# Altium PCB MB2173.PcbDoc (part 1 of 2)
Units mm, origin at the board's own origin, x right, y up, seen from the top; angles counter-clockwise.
Board outline 55.25 x 31 mm, 2 copper layers (Top Layer, Bottom Layer), stack 0.603 mm thick; 45 components, 48 nets, 188 pads, 868 vias.
Unrouted connection lines stored in the file: 99.
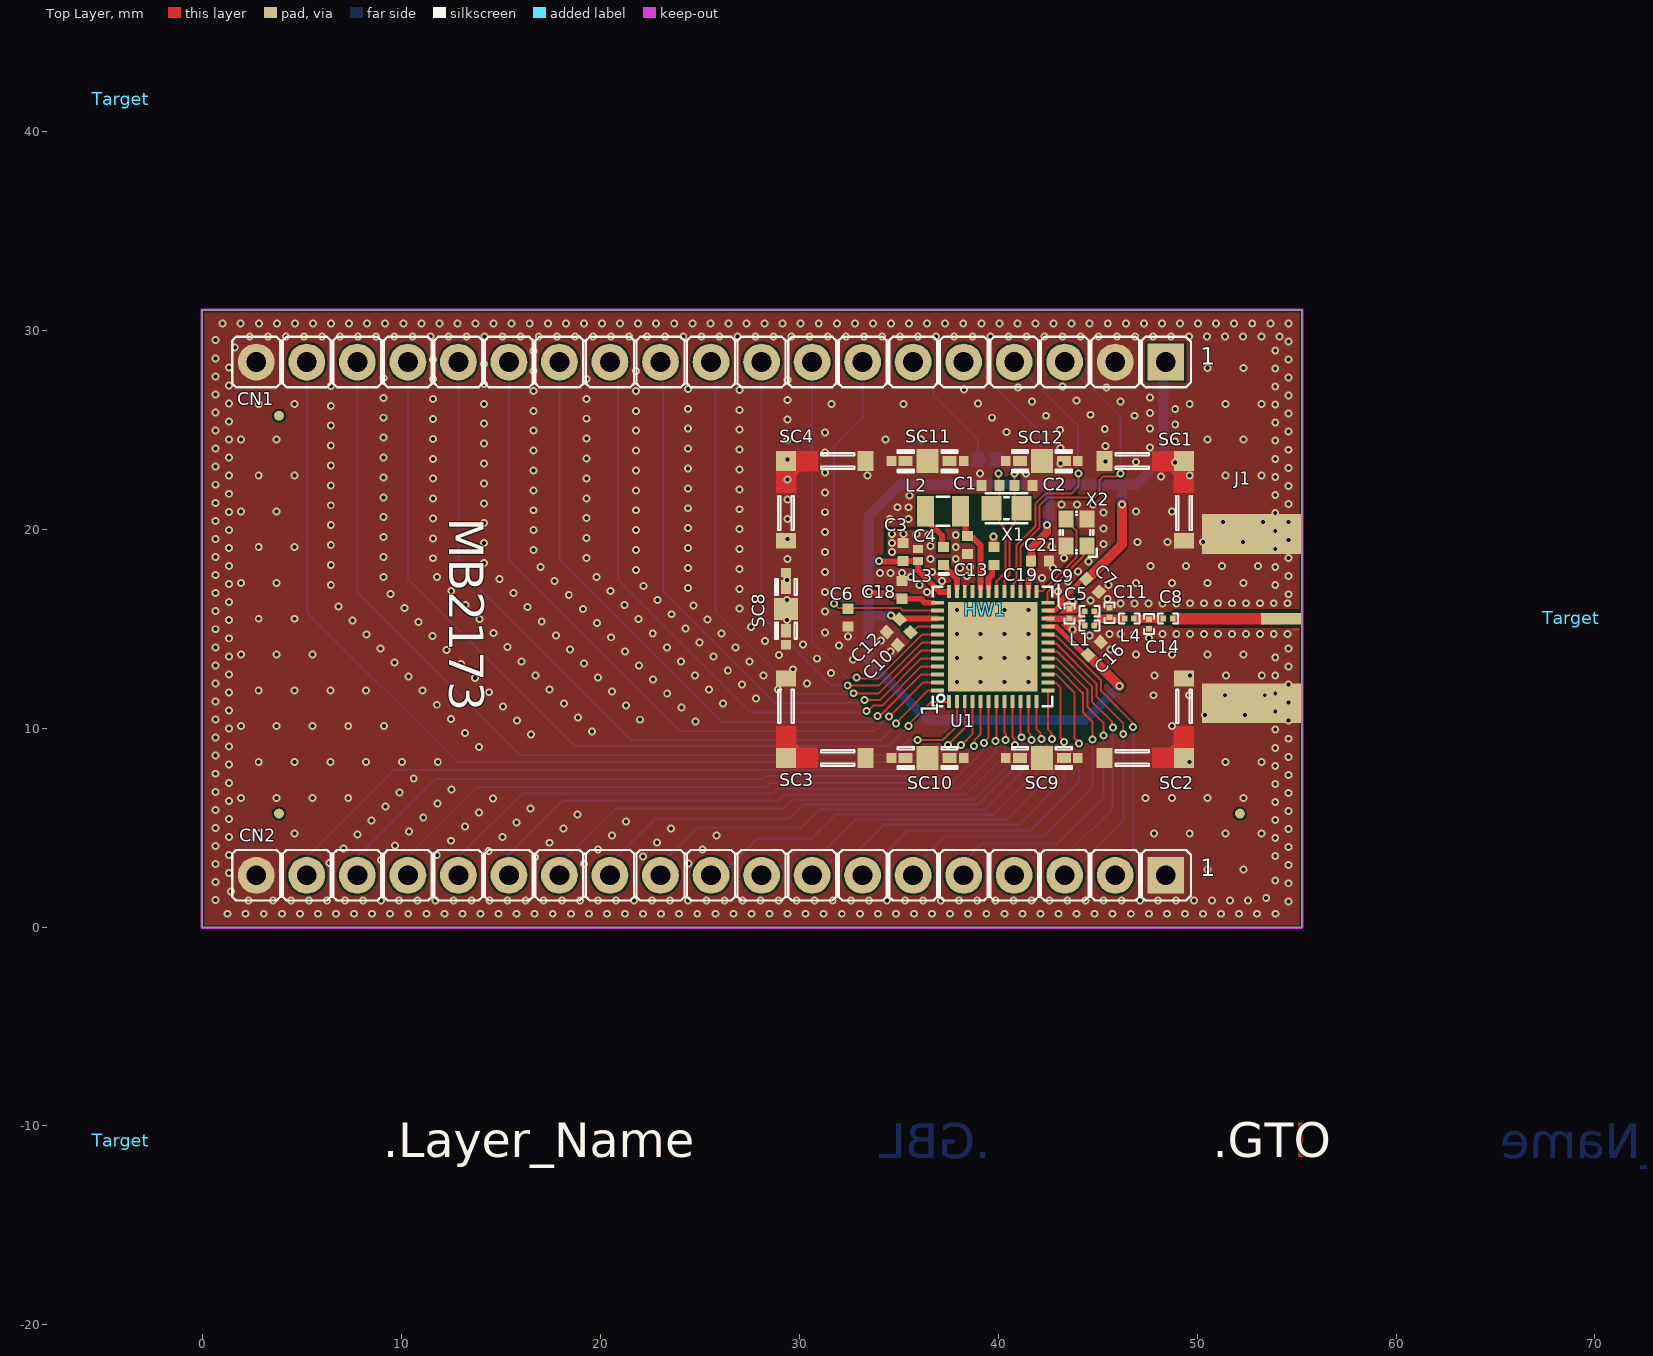
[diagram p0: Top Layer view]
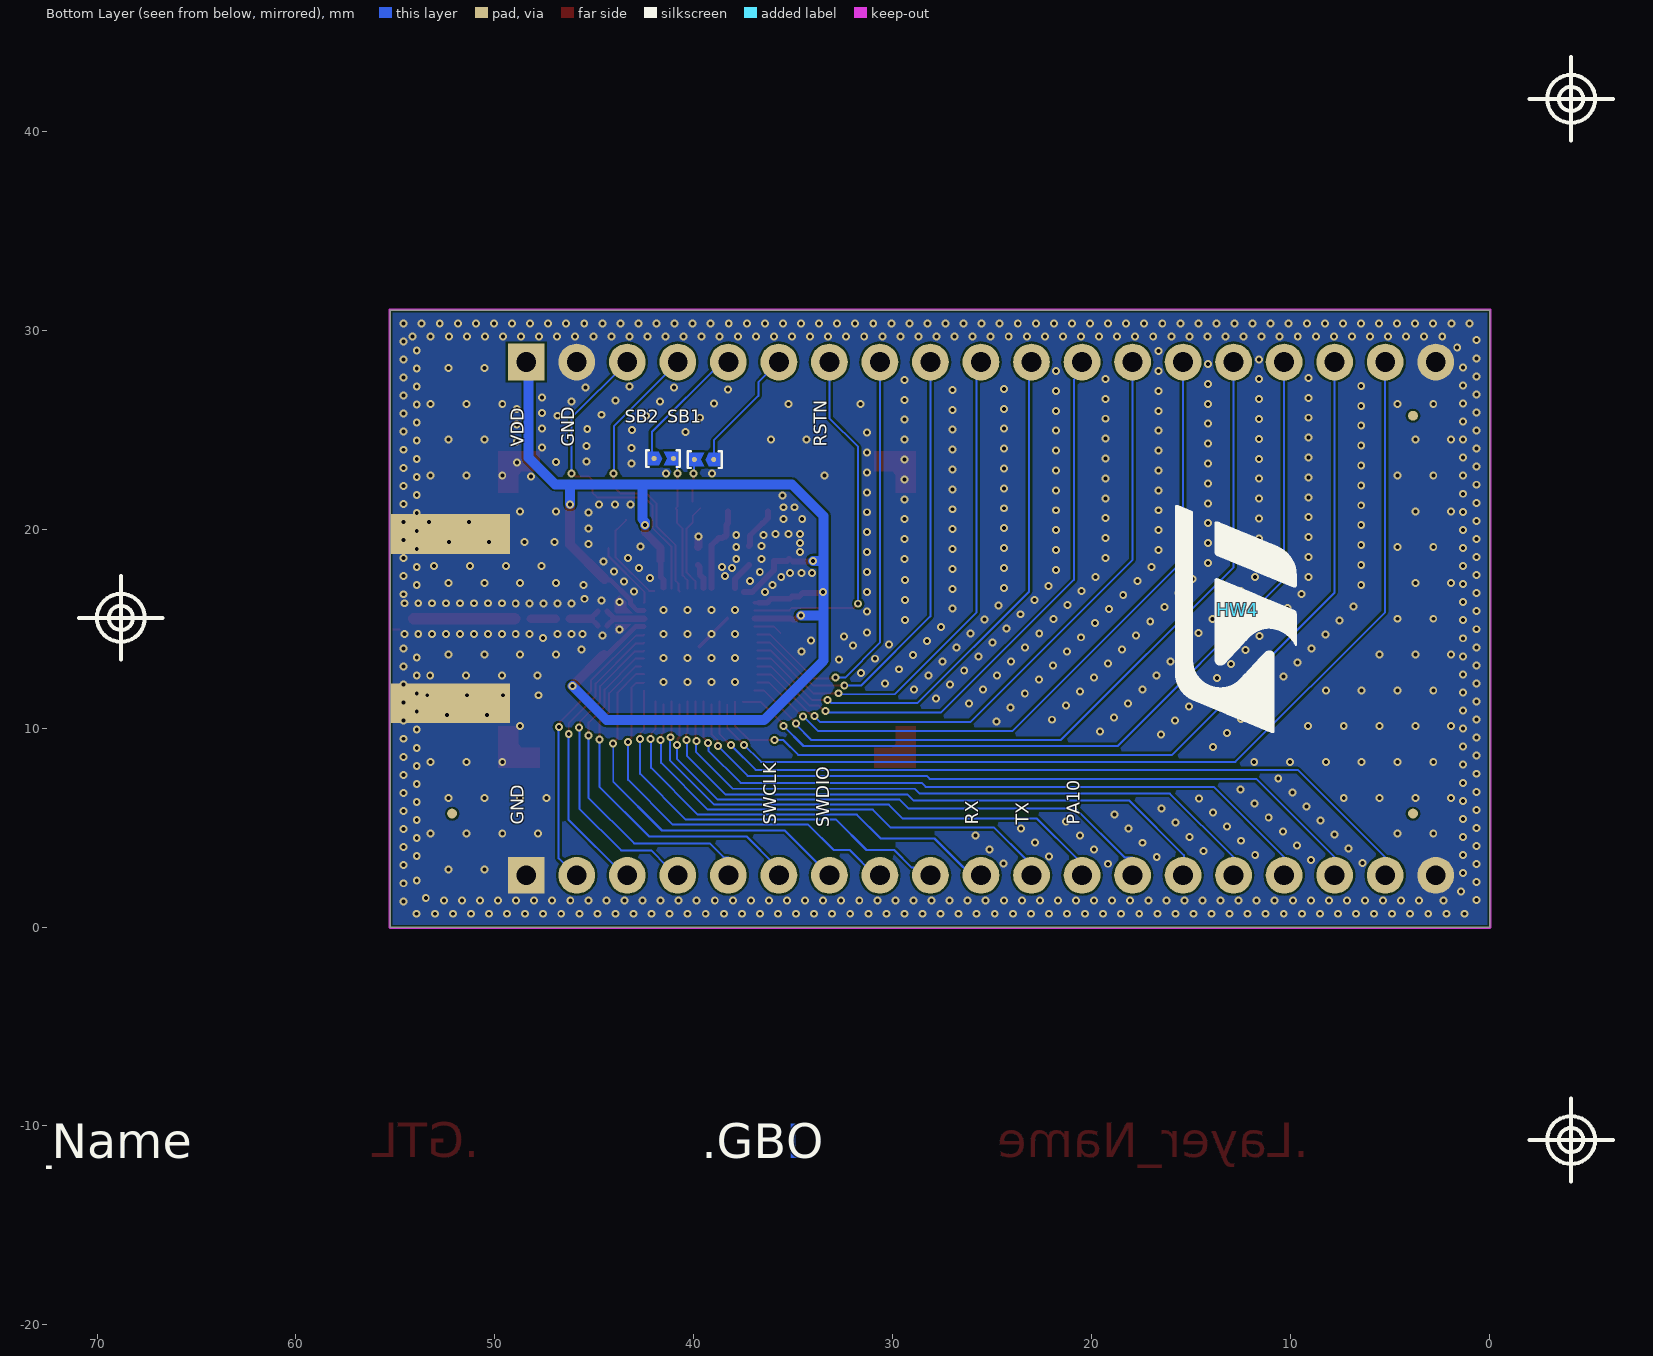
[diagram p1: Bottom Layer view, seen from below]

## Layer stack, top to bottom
Top Solder: solder mask 0.02, Solder Resist, Dk 3.5
Top Layer: signal copper 0.035
Dielectric 1: dielectric 0.533, TU-768 (3 x 7628), Dk 4.6
Bottom Layer: signal copper 0.035
Bottom Solder: solder mask 0.02, Solder Resist, Dk 3.5

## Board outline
0,0 0,31 55.25,31 55.25,0

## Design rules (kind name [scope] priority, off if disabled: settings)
Clearance Clearance_RF [InNet('NetC5_1')] p1: gap=0.1 ignorepadtopadclearanceinfootprint=FALSE
Clearance [All] p2: gap=0.1 ignorepadtopadclearanceinfootprint=FALSE
HoleToHoleClearance [All] p1: gap=0.15 allowstackedmicrovias=TRUE
MinimumSolderMaskSliver [All] p1: minsoldermaskwidth=0
ParallelSegment [All] p1: limit=10 gap=0.3
PlaneClearance [All] p1: clearance=0
PlaneConnect [InNet('GND')] p1: planeconnectstyle=Direct reliefexpansion=0.508 reliefentries=4 reliefconductorwidth=0.254 reliefairgap=0.254
PolygonConnect [InNet('GND')] p1: connectstyle=Direct reliefconductorwidth=0.254 reliefentries=4 polygonreliefangle="90 Angle" airgapwidth=0.254
RoutingVias [All] p1: holewidth=0.2 width=0.4 viastyle="Through Hole" minholewidth=0.2 minwidth=0.4 maxholewidth=0.2 maxwidth=0.4
SilkToSilkClearance [All] p1: silktosilkclearance=0
SilkToSolderMaskClearance [IsPad] p1: minsilkscreentomaskgap=0 clearancetoexposedcopper=TRUE
SolderMaskExpansion [All] p1: expansion=0.102 istentingtop=FALSE
Width [All] p1: maxlimit=0.7 minlimit=0.1 preferedwidth=0.1
24 further rules are at their usual default settings.

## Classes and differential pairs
component class MB2173: C1 C2 C3 C4 C5 C6 C7 C8 C10 C11 C12 C13 C14 C16 C18 C19 C21 CN1 CN2 L1 L2 L3 L4 SB1 SB2 SC1 SC2 SC3 SC4 SC8 SC9 SC10 SC11 SC12 U1 X1 X2

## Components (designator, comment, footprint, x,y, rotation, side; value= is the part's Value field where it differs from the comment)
C1 "Capacitor" C0402 39.617,22.2 r180 top value=10pF
C2 "Capacitor" C0402 41.267,22.2 r180 top value=10pF
C3 "Capacitor" C0402 35.217,18.85 r270 top value=4.7uF
C4 "Capacitor" C0201_H0P3 35.967,18.7 r270 top value=100nF
C5 "Capacitor" 0_5p_capacitor_SMD_0201 44.593,15.871 r90 top value=0.3pF
C6 "Capacitor" C0402 32.45,15.55 r270 top value=10nF
C7 "Capacitor" C0402 44.746,17.168 r135 top value=1uF
C8 "Capacitor" 20p_capacitor_SMD_0201 48.538,15.5 r90 top value=20pF
C9 "Capacitor" 0_8p_capacitor_SMD_0201 43.591,15.755 r0 top value=0.8pF
C10 "Capacitor" C0402 35.267,14.5 r225 top value=100nF
C11 "Capacitor" 1_5p_capacitor_SMD_0201 45.595,15.8 r0 top value=1.5pF
C12 "Capacitor" C0402 34.717,15.15 r45 top value=1uF
C13 "Capacitor" C0402 38.45,19.2 r90 top value=4.7uF
C14 "Capacitor" 0_8p_capacitor_SMD_0201 47.573,15.235 r180 top value=0.8pF
C16 "Capacitor" C0402 44.837,14 r225 top value=1uF
C18 "Capacitor" C0402 35.167,16.95 r270 top value=1uF
C19 "Capacitor" C0402 39.787,18.65 r270 top value=0.22uF
C21 "Capacitor" C0402 42.1,18.4 r180 top value=1uF
CN1 "Header 19x1" header_19x1 25.565,28.4 r180 top locked
CN2 "Header 19x1" header_19x1 25.565,2.6 r180 top locked
Designator16 "Comment" IMPEDANCE_TABLE 92.199,-23.657 r0 top
HW1 "S02-20150300" SHIELD_HARWIN_S02-20150300_15X20_H3 39.344,15.964 r90 top locked
HW4 "Logo" LOGO_ST 12.65,15.95 r90 bottom
J1 "SMA_connector" SMA_AMPHENOL_132415 54.225,15.5 r180 top locked
L1 "Inductor" 2n4_inductor_SMD_0201 44.594,15.146 r90 top value=2.4nH
L2 "Inductor" IND_0805_MURATA_LQM21 37.225,20.9 r180 top value=10uH
L3 "Inductor" C0402 37.25,18.65 r270 top value=22nH
L4 "Inductor" 3n3_inductor_SMD_0201 46.592,15.5 r90 top value=3.3nH
SB1 "SB_ON" SOLDER-BRIDGE_R0402-0R 39.45,23.5 r0 bottom value=0R
SB2 "SB_ON" SOLDER-BRIDGE_R0402-0R 41.55,23.55 r180 bottom value=0R
SC1 "Shield-clip_S0951-46R" CLIP_HARWIN_S0981-46R 49.337,23.418 r90 top value=S0981-46R
SC2 "Shield-clip_S0951-46R" CLIP_HARWIN_S0981-46R 49.337,8.5 r0 top value=S0981-46R
SC3 "Shield-clip_S0951-46R" CLIP_HARWIN_S0981-46R 29.337,8.5 r270 top locked value=S0981-46R
SC4 "Shield-clip_S0951-46R" CLIP_HARWIN_S0981-46R 29.337,23.418 r180 top value=S0981-46R
SC8 "Shield-clip_S0951-46R" CLIP_HARWIN_S0951-46R 29.337,15.993 r270 top value=S0951-46R
SC9 "Shield-clip_S0951-46R" CLIP_HARWIN_S0951-46R 42.198,8.5 r180 top value=S0951-46R
SC10 "Shield-clip_S0951-46R" CLIP_HARWIN_S0951-46R 36.448,8.5 r180 top value=S0951-46R
SC11 "Shield-clip_S0951-46R" CLIP_HARWIN_S0951-46R 36.448,23.418 r180 top value=S0951-46R
SC12 "Shield-clip_S0951-46R" CLIP_HARWIN_S0951-46R 42.198,23.418 r180 top value=S0951-46R
Target "" "Target PCB" -4.1,41.628 r90 top
Target "" "Target PCB" 68.8,15.54 r90 top
Target "" "Target PCB" -4.1,-10.71 r90 top
U1 "STM32WB07" ICC_QFN48-EPAD-4P5X4P5_6X6_P040 39.72,14.1 r90 top
X1 "XTAL_2_PINS" CRY_NX2012SA_2P 40.417,21.05 r0 top value=32.768kHz
X2 "XTAL_4_PINS" CRY_NX2016SA_4P 43.937,19.831 r90 top value=32MHz

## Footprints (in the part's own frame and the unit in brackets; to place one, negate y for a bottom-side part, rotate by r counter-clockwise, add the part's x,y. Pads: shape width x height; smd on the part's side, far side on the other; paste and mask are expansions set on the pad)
0_5p_capacitor_SMD_0201 [mm] "SMD 0201"
  rect 0.3x0.28 smd mask+0.05: 1(0.002,0.238) 2(0.002,-0.232)
  silkscreen extent -0.25,-0.51 0.25,0.51, body extent -0.15,-0.3 0.15,0.3, height 0.3
0_8p_capacitor_SMD_0201 [mm] "SMD 0201"
  rect 0.3x0.28 smd mask+0.05: 1(0.002,0.238) 2(0.002,-0.232)
  silkscreen extent -0.25,-0.51 0.25,0.51, body extent -0.15,-0.3 0.15,0.3, height 0.3
1_5p_capacitor_SMD_0201 [mm] "SMD 0201"
  rect 0.3x0.28 smd mask+0.05: 1(0.002,0.238) 2(0.002,-0.232)
  silkscreen extent -0.25,-0.51 0.25,0.51, body extent -0.15,-0.3 0.15,0.3, height 0.3
2n4_inductor_SMD_0201 [mm] "SMD 0201"
  rect 0.3x0.28 smd mask+0.05: 1(0.002,0.238) 2(0.002,-0.232)
  silkscreen extent -0.25,-0.51 0.25,0.51, body extent -0.15,-0.3 0.15,0.3, height 0.3
3n3_inductor_SMD_0201 [mm] "SMD 0201"
  rect 0.3x0.28 smd mask+0.05: 1(0.002,0.238) 2(0.002,-0.232)
  silkscreen extent -0.25,-0.51 0.25,0.51, body extent -0.15,-0.3 0.15,0.3, height 0.3
20p_capacitor_SMD_0201 [mm] "SMD 0201"
  rect 0.3x0.28 smd mask+0.05: 1(0.002,0.238) 2(0.002,-0.232)
  silkscreen extent -0.25,-0.51 0.25,0.51, body extent -0.15,-0.3 0.15,0.3, height 0.3
C0201_H0P3 [mm] "MCD-00699"
  rect 0.4x0.5 smd mask+0.05: 1(-0.3,0) 2(0.3,0)
  body extent -0.32,-0.17 0.32,0.17, height 0.33
C0402 [mm]
  rect 0.51x0.56 smd mask+0.05: 1(-0.45,0) 2(0.45,0)
  body extent -0.5,-0.3 0.5,0.3, height 0.4
CLIP_HARWIN_S0951-46R [mm] "MCD-01587_CLIP-X1"
  rect 0.48x0.5 smd mask+0.1: 1(-1.81,0) 1(1.81,0)
  rect 0.7x0.5 smd mask+0.1: 1(-1.1,0) 1(1.1,0)
  rect 1.1x1.2 smd mask+0.1: 1(0,0)
  silkscreen extent -1.5,-0.55 1.5,0.55, body extent -2.05,-0.65 2.05,0.65, height 1.28
CLIP_HARWIN_S0981-46R [mm] "MCD-02164"
  rect 0.8x1 smd mask+0.05: 1(-4,0)
  rect 1x0.8 smd mask+0.05: 1(0,4)
  rect 1x1 smd mask+0.05: 1(0,0)
  Top Layer region: -1.6,-0.5 0.5,-0.5 0.5,1.6 -0.5,1.6 -0.5,0.7 -0.7,0.5 -1.6,0.5
  silkscreen extent -3.45,-0.4 0.4,3.45, body extent -4.3,-0.46 0.46,4.3, height 1.4
CRY_NX2012SA_2P [mm]
  rect 1x1.25 smd mask+0.05: 1(-0.75,0) 2(0.75,0)
  silkscreen extent -1.05,-0.75 1.05,0.75, body extent -1.05,-0.63 1.05,0.63, height 0.6
CRY_NX2016SA_4P [mm]
  rect 0.85x0.75 smd mask+0.05: 1(-0.675,-0.525) 2(0.675,-0.525) 3(0.675,0.525) 4(-0.675,0.525)
  silkscreen extent -1.22,-1.02 1.05,0.85, body extent -1.05,-0.85 1.05,0.85, height 0.7
header_19x1 [mm] "MCD-01897"
  rect 1.85x1.85 / inner round 1.85 / far side rect 1.85x1.85 hole 1 mask+0.05: 1(-22.86,0)
  round 1.85 hole 1 mask+0.05: 2(-20.32,0) 3(-17.78,0) 4(-15.24,0) 5(-12.7,0) 6(-10.16,0) 7(-7.62,0) 8(-5.08,0) 9(-2.54,0) 10(0,0) 11(2.54,0) 12(5.08,0) 13(7.62,0) 14(10.16,0) 15(12.7,0) 16(15.24,0) 17(17.78,0) 18(20.32,0) 19(22.86,0)
  silkscreen extent -24.13,-1.27 24.07,1.27, body extent -24.26,-1.27 21.59,1.27, height 8.38
ICC_QFN48-EPAD-4P5X4P5_6X6_P040 [mm] "MCD-03488"
  rect 0.65x0.2 smd mask+0.05: 1(-2.775,2.2) 2(-2.775,1.8) 3(-2.775,1.4) 4(-2.775,1) 5(-2.775,0.6) 6(-2.775,0.2) 7(-2.775,-0.2) 8(-2.775,-0.6) 9(-2.775,-1) 10(-2.775,-1.4) 11(-2.775,-1.8) 12(-2.775,-2.2) 25(2.775,-2.2) 26(2.775,-1.8) 27(2.775,-1.4) 28(2.775,-1) 29(2.775,-0.6) 30(2.775,-0.2) 31(2.775,0.2) 32(2.775,0.6) 33(2.775,1) 34(2.775,1.4) 35(2.775,1.8) 36(2.775,2.2)
  rect 0.2x0.65 smd mask+0.05: 13(-2.2,-2.775) 14(-1.8,-2.775) 15(-1.4,-2.775) 16(-1,-2.775) 17(-0.6,-2.775) 18(-0.2,-2.775) 19(0.2,-2.775) 20(0.6,-2.775) 21(1,-2.775) 22(1.4,-2.775) 23(1.8,-2.775) 24(2.2,-2.775) 37(2.2,2.775) 38(1.8,2.775) 39(1.4,2.775) 40(1,2.775) 41(0.6,2.775) 42(0.2,2.775) 43(-0.2,2.775) 44(-0.6,2.775) 45(-1,2.775) 46(-1.4,2.775) 47(-1.8,2.775) 48(-2.2,2.775)
  rect 4.5x4.5 smd mask+0.05: 49(0,0)
  silkscreen extent -3,-3 3,3, body extent -3,-3 3,3, height 0.91
IMPEDANCE_TABLE [mm]
IND_0805_MURATA_LQM21 [mm] "MCD-02317"
  rect 0.85x1.55 smd mask+0.05: 1(-0.875,0) 2(0.875,0)
  silkscreen extent -0.33,-0.72 0.33,0.72, body extent -1.1,-0.72 1.1,0.72, height 1.45
LOGO_ST [mm]
  silkscreen extent -6.18,-2.95 5.25,3.14
SHIELD_HARWIN_S02-20150300_15X20_H3 [mm] "MCD-03126"
  body extent -7.6,-10.1 7.6,10.1, height 3.25
SMA_AMPHENOL_132415 [mm]
  rect 2.05x0.58 smd mask+0: 1(0,0)
  rect 5x2 smd: 2(1.475,4.25) 2(1.475,-4.25)
  rect 6x2 smd far side: 2(1.975,4.25) 2(1.975,-4.25)
  body extent -10.55,-4.76 4.36,4.76, height 4.11
SOLDER-BRIDGE_R0402-0R [mil] "MCD-01619"
  round 10 smd paste-393.7: 1(-17.72,0) 2(20.67,0)
  Top Layer region: -30.51,-13.78 -30.51,13.78 -8.37,13.78 -1.48,0 -8.37,-13.78
  Top Layer region: 1.48,13.78 8.37,0 1.48,-13.78 30.51,-13.78 30.51,13.78
  silkscreen extent -33,-17 33,17, body extent -20,-12 20,12, height 14
"Target PCB" [mm] "TargetA"

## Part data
C1 C2: library part MCD-00015, "Capacitor, MLCC, 10pF, 50V, NPO, +/-5%, 0402, T=0.5mm", Manufacturer=YAGEO, Manufacturer_Part_Number=CC0402JRNPO9BN100, Package=0402
C3 C13: library part MCD-03431, "Capacitor, MLCC, 4.7uF, X5R, 10V, +/-20%, 0402, T=0.5mm", Manufacturer=MURATA, Manufacturer_Part_Number=GRM155R61A475MEAAD, Package=0402
C4: library part MCD-01535, "Capacitor, MLCC,100nF, 10V, X5R, +/-10%, 0201, T=0.3mm", Manufacturer=MURATA, Manufacturer_Part_Number=GRM033R61A104KE15, Package=0201
C5: library part MCD-02284_4, "0201 0.3 pF 25 V ±0.05 pF Tolerance C0G SMT Multilayer Ceramic Capacitor", Manufacturer=Murata, Manufacturer Part Number=GJM0335C1ER30WB01D, Supplier Part Number 1=490-8073-1-ND
C6: library part MCD-00011, "Capacitor, MLCC, 10nF, 16V, X7R, +/-10%, 0402, T=0.5mm", Manufacturer=YAGEO, Manufacturer_Part_Number=CC0402KRX7R7BB103, Package=0402
C7 C12 C16 C18 C21: library part MCD-03432, "Capacitor, MLCC, 1uF, X7R, 6.3V,+/- 10%, 0402, T=0.5mm", Manufacturer=MURATA, Manufacturer_Part_Number=GRM155R70J105KA12, Package=0402
C8: library part MCD-03543, "Capacitor, MLCC, 20pF, 25V, COG, +/-2%, 0201, T=0.3mm", Manufacturer=MURATA, Manufacturer_Part_Number=GJM0335C1E200GB01, Package=0201
C9 C14: library part MCD-02284_1, "Multilayer Ceramic Capacitor, 0.8 pF, 25 V, ± 0.05pF, C0G (NP0), 0201 [0603 Metric]", Manufacturer=Murata, Manufacturer Part Number=GJM0335C1ER80WB01D, Temperature Coefficient=30ppm/°C
C10: library part MCD-02355, "Capacitor, MLCC, 100nF, 25V, X7R, +/-10%, 0402, T=0.5mm", Manufacturer=WALSIN, Manufacturer_Part_Number=0402B104K250CT, Package=0402
C11: library part MCD-02284_3, "Multilayer Ceramic Capacitor, 1.5 pF, 25 V, ± 0.1pF, C0G (NP0), 0201 [0603 Metric]", Case Code (Imperial)=0201, Case Code (Metric)=0603, Dielectric=C0G, Manufacturer=Murata, Manufacturer Part Number=GJM0335C1E1R5BB01D, Max Operating Temperature=125°C, Min Operating Temperature=-55°C, Package Quantity=15000, Supplier Part Number 1=490-11175-1-ND, Voltage Rating=25V
C19: library part MCD-03483, "Capacitor, MLCC, 0.22uF, X5R, 6.3V, +/-10%, 0402, T=0.5mm", Manufacturer=YAGEO, Manufacturer_Part_Number=CC0402KRX5R5BB224, Package=0402
CN1 CN2: library part HEADER_19X1, "Header, 18x1, 2.54mm, VR, TH, T=5.84mm/8.38mm", Manufacturer=SAMTEC, Manufacturer_Part_Number=TSW-118-07-L-S, Package=TSW
Designator16: library part MCD-00279
HW1: library part MCD-03126, "RFI shield can, 20x15x3mm", Manufacturer=HARWIN, Package=20x15x3mm
HW4: library part MCD-00625, "\"STMicroelectronics\" logo footprint for PCB"
J1: "Rf Connector, Sma End Launch Recept Jack For .032\" Pcb / Individual Bag", Manufacturer="Amphenol Connex", Manufacturer Part Number=132415, Supplier Part Number 1=132415-ND
L1: library part MCD-03552, "Inductor RF Chip Thin Film 2.4nH 0.1nH 500MHz 14Q-Factor 500mA 200mOhm DCR 0201 Paper T/R", Manufacturer=Murata, Manufacturer Part Number=LQP03TN2N4B02D, Supplier Part Number 1=490-6724-1-ND
L2: library part MCD-03438, "Inductor, MLCC, 10uH, +/-20%, 300mA, 845mR, 0805, T=1.45mm", Manufacturer=MURATA, Manufacturer_Part_Number=LQM21DN100M70L, Package=0805
L3: library part MCD-03439, "Inductor, MLCC, 22nH, +/-2%, 350mA, 0.58R, 0402, T=1.45mm", Manufacturer=MURATA, Manufacturer_Part_Number=LQG15HN22NG02D, Package=0402
L4: library part MCD-03552_1, "Inductor RF Chip Thin Film 3.3nH 0.1nH 500MHz 14Q-Factor 450mA 250mOhm DCR 0201 Paper T/R", Manufacturer=Murata, Manufacturer Part Number=LQP03TN3N3B02D, Supplier Part Number 1=490-6728-1-ND
SB1 SB2: library part MCD-01618, "Resistor, 0R, SB0402, 5%, 0.063W", Manufacturer=YAGEO, Manufacturer_Part_Number=RC0402JR-070RL, Package=0402
SC1 SC2 SC3 SC4: library part MCD-02164, "Shield clip Harwin S0981-46R to fix RF shielded cavity", Manufacturer=HARWIN, Manufacturer_Part_Number=S0981-46R, Package=0.8x4.7x1.4mm
SC8 SC9 SC10 SC11 SC12: library part MCD-01587, "RFI shield clip mini TIN SMD", Manufacturer=HARWIN, Manufacturer_Part_Number=S0951-46R, Package=1.1x3.9mm
U1: library part MCD-03836, "IC, Bluetooth Low Energy wireless SoC, QFN48", Manufacturer=STMICROELECTRONICS, Manufacturer_Part_Number=STM32WB07CCV6UTR, Package=QFN48
X1: library part MCD-01445, "Crystal, 32.768kHz, 7pF, +/-20ppm, 80K, 2.05x1.2mm", Manufacturer=NDK, Manufacturer_Part_Number=NX2012SA-32.768KHZ-EXS00A-MU00389, Package=2.05x1.2mm
X2: library part MCD-01446, "Crystal, 32MHz, 8pF, +/-10ppm, 60R, 2x1.6mm", Manufacturer=NDK, Manufacturer_Part_Number=NX2016SA-32MHZ-EXS00A-CS06654, Package=2x1.6mm

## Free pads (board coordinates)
  round 0.5 all layers, no hole mask+0: 1(3.85,5.7) 1(3.85,25.7) 1(52.15,5.7)
  round 0.508 on Mech16: 1(20.768,-18.512) 1(69.616,-18.512)

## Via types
v1: diameter 0.4, hole 0.2, Top Layer to Bottom Layer, tented both sides, 868 vias

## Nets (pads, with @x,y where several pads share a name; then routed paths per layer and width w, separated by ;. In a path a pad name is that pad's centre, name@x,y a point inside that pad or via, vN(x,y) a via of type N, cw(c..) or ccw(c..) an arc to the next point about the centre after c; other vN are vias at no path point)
GND: C1.2 C2.1 C3.1 C4.1 C6.2 C7.1 C9.1 C10.2 C11.1 C12.1 C13.1 C14.1 C16.1 C18.1 C19.1 C21.1 CN1.2 CN1.19 CN2.1 CN2.19 J1.2 SC1.1 SC2.1 SC3.1 SC4.1 SC8.1 SC9.1 SC10.1 SC11.1 SC12.1 U1.34 U1.49 X2.2 X2.4 | length 2.5
  Top Layer w0.2: U1.49@38.32,15.5 U1.49@39.72,14.1
  Top Layer w0.4: v1(39.769,19.631) 39.769,19.119 C19.1@39.787,19.1
  other v1: 1.265,0.666 2.173,0.666 3.081,0.666 3.989,0.666 4.897,0.666 5.805,0.666 6.713,0.666 7.621,0.666 8.529,0.666 9.437,0.666 10.345,0.666 11.253,0.666 12.161,0.666 13.069,0.666 13.977,0.666 14.885,0.666 15.793,0.666 16.701,0.666 17.609,0.666 18.517,0.666 19.425,0.666 20.333,0.666 21.241,0.666 22.149,0.666 23.057,0.666 23.965,0.666 24.873,0.666 25.781,0.666 26.689,0.666 27.597,0.666 28.505,0.666 29.413,0.666 30.321,0.666 31.229,0.666 32.137,0.666 33.045,0.666 33.953,0.666 34.861,0.666 35.769,0.666 36.677,0.666 37.585,0.666 38.493,0.666 39.401,0.666 40.309,0.666 41.217,0.666 42.125,0.666 43.033,0.666 43.941,0.666 44.849,0.666 45.757,0.666 46.665,0.666 47.573,0.666 48.481,0.666 49.389,0.666 50.297,0.666 51.205,0.666 52.113,0.666 53.021,0.666 53.929,0.666 54.588,1.291 2.322,1.326 3.535,1.326 4.443,1.326 5.351,1.326 6.259,1.326 7.167,1.326 8.075,1.326 8.983,1.326 9.891,1.326 10.799,1.326 11.707,1.326 12.615,1.326 13.523,1.326 14.431,1.326 15.339,1.326 16.247,1.326 17.155,1.326 18.063,1.326 18.971,1.326 19.879,1.326 20.787,1.326 21.695,1.326 22.603,1.326 23.511,1.326 24.419,1.326 25.327,1.326 26.235,1.326 27.143,1.326 28.051,1.326 28.959,1.326 29.867,1.326 30.775,1.326 31.683,1.326 32.591,1.326 33.499,1.326 34.407,1.326 35.315,1.326 36.223,1.326 37.131,1.326 38.039,1.326 38.947,1.326 39.855,1.326 40.763,1.326 41.671,1.326 42.579,1.326 43.487,1.326 44.395,1.326 45.303,1.326 46.211,1.326 47.119,1.326 48.027,1.326 48.935,1.326 49.843,1.326 50.751,1.326 51.659,1.326 52.567,1.326 0.666,1.348 53.474,1.45 1.445,1.791 54.588,2.199 0.666,2.256 53.928,2.34 1.326,2.71 50.529,2.895 52.329,2.895 54.588,3.107 0.666,3.164 19.179,3.179 24.436,3.186 6.379,3.229 8.979,3.379 16.729,3.529 22.136,3.536 53.928,3.561 1.326,3.618 11.779,3.629 14.379,3.829 19.886,3.886 25.143,3.893 7.086,3.936 54.588,4.015 0.666,4.072 9.686,4.086 17.436,4.236 22.843,4.243 12.486,4.336 53.928,4.469 1.326,4.526 15.086,4.536 20.593,4.593 25.85,4.6 7.793,4.643 2.829,4.695 4.629,4.695 47.829,4.695 49.629,4.695 51.429,4.695 53.229,4.695 10.393,4.793 54.588,4.923 18.143,4.943 23.55,4.95 0.666,4.98 13.193,5.043 15.793,5.243 21.3,5.3 8.5,5.35 53.928,5.377 1.326,5.434 11.1,5.5 18.85,5.65 13.9,5.75 54.588,5.831 0.666,5.888 16.5,5.95 9.207,6.057 11.807,6.207 53.928,6.285 1.326,6.342 14.607,6.457 1.929,6.495 3.729,6.495 5.529,6.495 7.329,6.495 47.4,6.495 48.729,6.495 50.529,6.495 52.329,6.495 54.588,6.739 9.914,6.764 0.666,6.796 12.514,6.914 53.928,7.193 1.326,7.25 10.621,7.471 54.588,7.647 0.666,7.704 53.928,8.101 1.326,8.158 2.829,8.295 4.629,8.295 6.429,8.295 8.229,8.295 10.029,8.295 11.829,8.295 49.629,8.295 51.429,8.295 53.229,8.295 54.588,8.555 0.666,8.612 53.928,9.009 1.326,9.066 13.9,9.05 54.588,9.463 0.666,9.52 16.521,9.679 13.193,9.757 19.578,9.822 53.928,9.917 1.326,9.974 1.929,10.095 3.729,10.095 5.529,10.095 7.329,10.095 9.129,10.095 48.729,10.095 24.778,10.322 15.814,10.386 54.588,10.371 22.006,10.419 0.666,10.428 12.486,10.464 18.871,10.529 50.4,10.65 52.4,10.65 53.928,10.825 1.326,10.882 24.071,11.029 15.107,11.093 21.299,11.126 11.779,11.171 26.171,11.229 18.164,11.236 54.588,11.279 0.666,11.336 27.821,11.479 47.8,11.65 49.6,11.65 51.4,11.65 53.4,11.65 23.364,11.736 53.928,11.733 1.326,11.79 14.4,11.8 20.592,11.833 11.072,11.878 2.829,11.895 4.629,11.895 6.429,11.895 8.229,11.895 17.457,11.943 25.464,11.936 28.921,11.929 27.114,12.186 54.588,12.187 0.666,12.244 30.4,12.25 37.922,12.325 39.122,12.325 40.322,12.325 41.522,12.325 22.657,12.443 13.693,12.507 19.885,12.54 10.364,12.586 16.75,12.65 24.757,12.643 28.214,12.636 47.85,12.65 49.65,12.65 51.45,12.65 53.25,12.65 53.928,12.641 1.326,12.698 31.601,12.778 26.407,12.893 29.693,12.957 54.588,13.095 0.666,13.152 21.95,13.15 12.986,13.214 19.178,13.247 9.657,13.293 16.043,13.357 24.05,13.35 27.507,13.343 32.701,13.436 30.894,13.485 37.922,13.525 39.122,13.525 40.322,13.525 41.522,13.525 53.928,13.549 1.326,13.606 25.7,13.6 28.986,13.664 1.929,13.695 3.729,13.695 5.529,13.695 46.929,13.695 48.729,13.695 50.529,13.695 52.329,13.695 34.587,13.85 21.243,13.857 12.278,13.922 45.637,13.95 18.471,13.954 8.95,14 54.588,14.003 26.8,14.05 0.666,14.06 15.336,14.064 23.343,14.057 31.994,14.143 30.187,14.192 24.993,14.307 28.279,14.371 34.1,14.4 1.326,14.514 47.581,14.518 20.536,14.564 32.45,14.6 11.571,14.629 17.763,14.662 44.587,14.65 8.243,14.707 37.922,14.725 39.122,14.725 40.322,14.725 41.522,14.725 45.587,14.725 46.157,14.725 46.857,14.725 48.256,14.725 48.952,14.725 49.652,14.725 50.352,14.725 51.052,14.725 51.752,14.725 52.452,14.725 53.152,14.725 53.852,14.725 54.552,14.725 22.636,14.764 26.093,14.757 14.628,14.772 31.287,14.8 43.737,14.95 0.666,14.968 24.286,15.014 27.572,15.078 19.828,15.272 10.864,15.336 17.056,15.369 1.326,15.422 7.536,15.414 29.384,15.443 21.928,15.472 25.386,15.464 2.829,15.495 4.629,15.495 13.921,15.479 23.578,15.722 31.287,15.85 0.666,15.876 37.922,15.925 39.122,15.925 40.322,15.925 41.522,15.925 19.121,15.979 27,16 10.157,16.043 16.349,16.076 6.829,16.121 13.214,16.186 21.221,16.179 24.678,16.172 46.157,16.266 46.857,16.266 47.557,16.266 48.256,16.266 48.952,16.266 49.652,16.275 50.352,16.275 51.052,16.275 51.752,16.275 52.452,16.275 53.152,16.275 53.852,16.275 54.552,16.275 1.326,16.33 43.737,16.34 22.871,16.429 44.631,16.418 29.384,16.443 45.5,16.5 18.414,16.686 54.588,16.727 9.45,16.75 0.666,16.784 15.642,16.783 31.287,16.85 36.415,16.848 12.507,16.893 20.514,16.886 43.012,16.876 27,17 24.4,17.05 22.164,17.136 6.45,17.2 36.037,17.2 45.537,17.2 53.928,17.181 1.326,17.238 1.929,17.295 3.729,17.295 46.929,17.295 48.729,17.295 50.529,17.295 52.329,17.295 43.512,17.376 17.707,17.393 37.167,17.4 29.384,17.443 14.935,17.49 42.199,17.55 9.1,17.6 11.8,17.6 19.807,17.593 35.606,17.585 54.588,17.635 38.441,17.65 0.666,17.692 34.05,17.8 34.587,17.8 35.167,17.8 31.287,17.85 36.685,17.851 44.02,17.871 21.8,17.95 27,18 24.4,18.05 38.087,18.05 42.75,18.05 53.928,18.089 17,18.1 38.587,18.1 1.326,18.146 47.65,18.15 49.45,18.15 51.25,18.15 53.05,18.15 6.45,18.2 14.15,18.3 44.534,18.384 29.4,18.5 36.6,18.5 37.867,18.5 11.595,18.537 54.588,18.543 19.3,18.55 43.318,18.557 0.666,18.6 9.1,18.6 31.287,18.85 34.667,18.85 16.65,18.95 21.8,18.95 27,19 53.928,18.997 1.326,19.054 24.4,19.05 2.829,19.095 4.629,19.095 37.867,19.1 36.6,19.15 42.68,19.138 6.45,19.2 45.287,19.25 14.15,19.3 34.667,19.3 47,19.35 48.5,19.35 50.3,19.35 52.3,19.35 54.588,19.451 0.666,19.508 29.4,19.5 11.595,19.537 19.3,19.55 9.1,19.6 36.5,19.7 37.867,19.7 34.667,19.75 35.241,19.75 35.891,19.75 31.287,19.85 53.928,19.905 1.326,19.962 16.65,19.95 21.8,19.95 27,20 45.287,20.034 24.4,20.05 6.45,20.2 14.15,20.3 51.3,20.35 53.3,20.35 54.588,20.359 0.666,20.416 29.4,20.5 34.55,20.5 35.5,20.5 11.595,20.537 19.3,20.55 9.1,20.6 45.287,20.828 53.928,20.813 31.287,20.85 1.326,20.87 1.929,20.895 3.729,20.895 46.929,20.895 48.729,20.895 16.65,20.95 21.8,20.95 27,21 24.4,21.05 34.95,21.1 35.5,21.1 6.45,21.2 43.187,21.25 43.972,21.25 44.765,21.25 54.588,21.267 14.15,21.3 0.666,21.324 29.4,21.5 11.595,21.537 19.3,21.55 9.1,21.6 35.55,21.7 53.928,21.721 1.326,21.778 31.287,21.85 16.65,21.95 21.8,21.95 27,22 24.4,22.05 54.588,22.175 6.45,22.2 0.666,22.232 14.15,22.3 29.4,22.5 11.595,22.537 19.3,22.55 9.1,22.6 48.186,22.636 53.928,22.629 1.326,22.686 2.829,22.695 4.629,22.695 33.429,22.695 49.629,22.695 51.429,22.695 53.229,22.695 39.093,22.8 41.387,22.8 31.287,22.85 16.65,22.95 21.8,22.95 27,23 24.4,23.05 54.588,23.083 0.666,23.14 6.45,23.2 14.15,23.3 43.137,23.3 48.893,23.343 45.387,23.4 46.936,23.386 29.4,23.5 11.595,23.537 19.3,23.55 53.928,23.537 1.326,23.594 9.1,23.6 31.287,23.85 16.65,23.95 21.8,23.95 27,24 54.588,23.991 0.666,24.048 24.4,24.05 43.137,24.084 47.643,24.093 45.387,24.184 6.45,24.2 14.15,24.3 48.9,24.4 53.928,24.445 1.326,24.502 1.929,24.495 3.729,24.495 29.4,24.5 34.329,24.495 36.129,24.495 50.529,24.495 52.329,24.495 11.595,24.537 19.3,24.55 9.1,24.6 31.287,24.85 40.407,24.893 54.588,24.899 16.65,24.95 21.8,24.95 0.666,24.956 27,25 43.107,24.993 24.4,25.05 45.357,25.043 47.637,25.05 6.45,25.2 48.9,25.25 14.15,25.3 53.928,25.353 1.326,25.41 29.4,25.5 11.595,25.537 19.3,25.55 9.1,25.6 39.7,25.6 42.4,25.7 46.85,25.7 44.65,25.75 54.588,25.807 47.637,25.834 0.666,25.864 16.65,25.95 21.8,25.95 27,26 24.4,26.05 48.9,26.05 6.45,26.2 53.928,26.261 2.829,26.295 4.629,26.295 31.629,26.295 35.229,26.295 49.629,26.295 51.429,26.295 53.229,26.295 1.326,26.318 14.15,26.3 38.993,26.307 41.693,26.407 46.143,26.407 43.943,26.457 29.4,26.5 11.595,26.537 19.3,26.55 9.1,26.6 47.637,26.628 54.588,26.715 0.666,26.772 16.65,26.95 21.8,26.95 27,27 38.286,27.014 24.4,27.05 40.986,27.114 45.436,27.114 43.236,27.164 53.928,27.169 6.45,27.2 1.326,27.226 14.15,27.3 29.4,27.5 11.595,27.537 19.3,27.55 9.1,27.6 54.588,27.623 0.666,27.68 16.65,27.95 21.8,27.95 50.529,28.095 52.329,28.095 53.928,28.077 1.326,28.134 14.15,28.3 54.588,28.531 11.595,28.537 0.666,28.588 16.65,28.95 53.928,28.985 1.625,29.131 54.588,29.439 0.666,29.496 2.378,29.674 3.286,29.674 4.194,29.674 5.102,29.674 6.01,29.674 6.918,29.674 7.826,29.674 8.734,29.674 9.642,29.674 10.55,29.674 11.458,29.674 12.366,29.674 13.274,29.674 14.182,29.674 15.09,29.674 15.998,29.674 16.906,29.674 17.814,29.674 18.722,29.674 19.63,29.674 20.538,29.674 21.446,29.674 22.354,29.674 23.262,29.674 24.17,29.674 25.078,29.674 25.986,29.674 26.894,29.674 27.802,29.674 28.71,29.674 29.618,29.674 30.526,29.674 31.434,29.674 32.342,29.674 33.25,29.674 34.158,29.674 35.066,29.674 35.974,29.674 36.882,29.674 37.79,29.674 38.698,29.674 39.606,29.674 40.514,29.674 41.422,29.674 42.33,29.674 43.238,29.674 44.146,29.674 45.054,29.674 45.962,29.674 46.87,29.674 47.778,29.674 48.686,29.674 49.594,29.674 50.502,29.674 51.41,29.674 52.318,29.674 53.226,29.674 54.134,29.674 1.016,30.334 1.924,30.334 2.832,30.334 3.74,30.334 4.648,30.334 5.556,30.334 6.464,30.334 7.372,30.334 8.28,30.334 9.188,30.334 10.096,30.334 11.004,30.334 11.912,30.334 12.82,30.334 13.728,30.334 14.636,30.334 15.544,30.334 16.452,30.334 17.36,30.334 18.268,30.334 19.176,30.334 20.084,30.334 20.992,30.334 21.9,30.334 22.808,30.334 23.716,30.334 24.624,30.334 25.532,30.334 26.44,30.334 27.348,30.334 28.256,30.334 29.164,30.334 30.072,30.334 30.98,30.334 31.888,30.334 32.796,30.334 33.704,30.334 34.612,30.334 35.52,30.334 36.428,30.334 37.336,30.334 38.244,30.334 39.152,30.334 40.06,30.334 40.968,30.334 41.876,30.334 42.784,30.334 43.692,30.334 44.6,30.334 45.508,30.334 46.416,30.334 47.324,30.334 48.232,30.334 49.14,30.334 50.048,30.334 50.956,30.334 51.864,30.334 52.772,30.334 53.68,30.334 54.588,30.334
NetC1_1: C1.1 SB1.2 U1.30 X1.1 | length 6.4
  Top Layer w0.1: X1.1@39.667,21.05 40.053,20.664 40.053,20.334 40.367,20.02 40.367,17.83 39.92,17.382 U1.30@39.92,17.025 ; C1.1@40.018,22.149 C1.1@40.067,22.1 ; v1(40.025,22.8) 40.025,22.242 C1.1@40.067,22.2 ; X1.1@40.067,21.4 C1.1@40.067,22.075
  Bottom Layer w0.1: 39.992,23.367 39.992,22.833 v1(40.025,22.8)
NetC2_2: C2.2 SB2.2 U1.29 X1.2 | length 6.8
  Top Layer w0.1: U1.29@40.32,17.025 40.32,17.433 40.567,17.68 40.567,20.03 40.851,20.314 40.851,20.984 40.917,21.05 40.817,21.15 40.817,22.1 C2.2@40.817,22.2 ; C2.2@40.817,22.2 v1(40.817,22.8)
  Bottom Layer w0.1: v1(40.817,22.8) 40.837,22.82 40.837,23.275 SB2.2@41.012,23.45
NetC5_1: C5.1 C9.2 L1.1 U1.22 | length 2.5
  Top Layer w0.28: 43.991,15.509 C5.1@44.355,15.873 ; 43.995,15.509 L1.1@44.356,15.149
  Top Layer w0.33: U1.22@42.495,15.5 43.988,15.5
